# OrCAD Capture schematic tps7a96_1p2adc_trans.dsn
size A
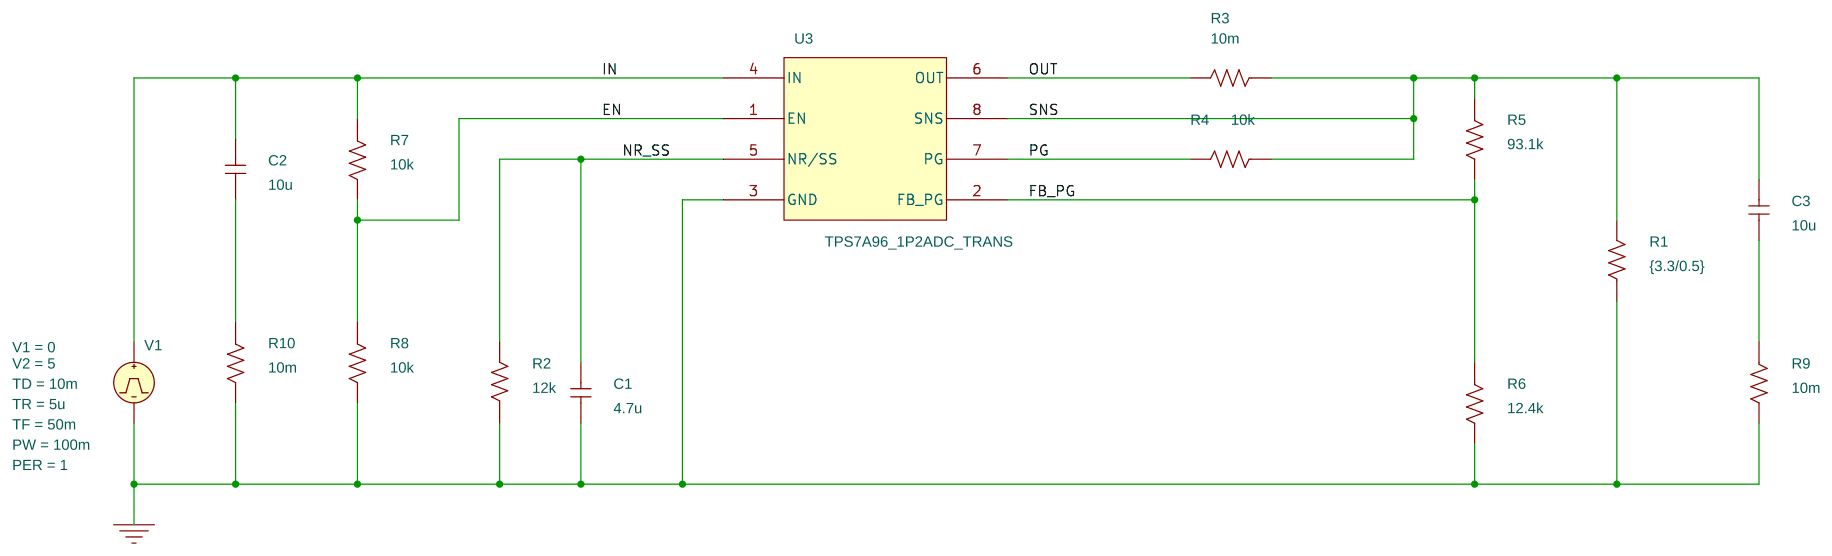
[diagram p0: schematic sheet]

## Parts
C1  4.7u  [RAD/CK05]
C2  10u  [RAD/CK05]
C3  10u  [RAD/CK05]
R1  {3.3/0.5}  [AX/RC05]
R2  12k  [AX/RC05]
R3  10m  [AX/RC05]
R4  10k  [AX/RC05]
R5  93.1k  [AX/RC05]
R6  12.4k  [AX/RC05]
R7  10k  [AX/RC05]
R8  10k  [AX/RC05]
R9  10m  [AX/RC05]
R10  10m  [AX/RC05]
U3  TPS7A96_1P2ADC_TRANS
V1  VPULSE

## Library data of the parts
C1-C3 = C
R1-R10 = R
U3 = TPS7A94_1ADC_TRANS_3: PSpiceTemplate: X^@REFDES  %EN %FB_PG %GND %IN %NR/SS %OUT %PG %SNS @MODEL
V1 = VPULSE: PER: 1; PW: 100m; TD: 10m; TF: 50m; TR: 5u; V1: 0; V2: 5

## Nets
0: C1.1 R1.1 R2.1 R6.2 R8.2 R9.2 R10.2 U3.3(GND) V1.2(-)
EN: R7.2 R8.1 U3.1(EN)
FB_PG: R5.2 R6.1 U3.2(FB_PG)
IN: C2.2 R7.1 U3.4(IN) V1.1(+)
NR_SS: C1.2 R2.2 U3.5(NR/SS)
OUT: R3.2 U3.6(OUT)
PG: R4.2 U3.7(PG)
SNS: C3.2 R1.2 R3.1 R4.1 R5.1 U3.8(SNS)
N240913: C2.1 R10.1
N241023: C3.1 R9.1
